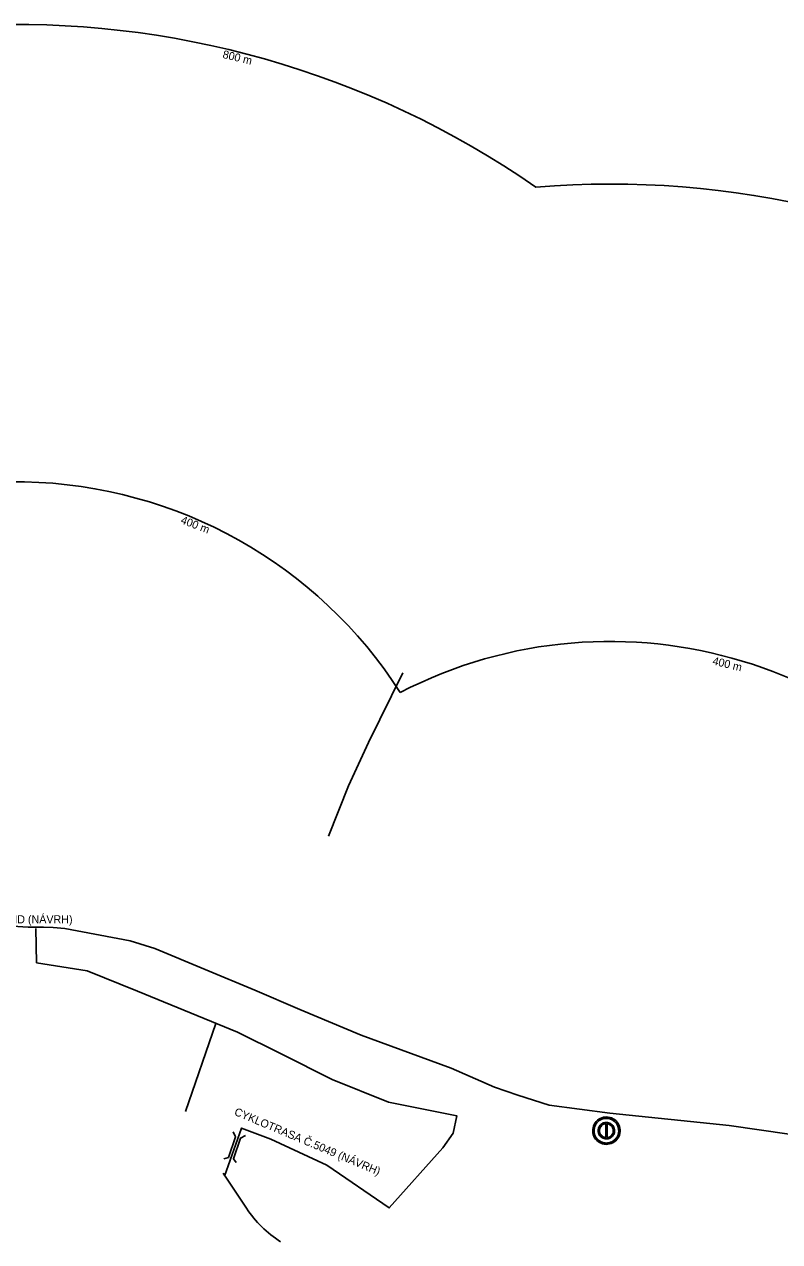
# Model space of a CAD drawing. Extents: x -520790 to -517278, y -1190021 to -1185077.
# Drawn here: x -518762 to -518101, y -1187441 to -1186376 of the extents above; entities that cross this region are included whole.
import ezdxf

# ---------------------------------------------------------------- set-up
doc = ezdxf.new("R2010")
doc.units = 0
for name, color, linetype in [('cyklostezka_n', 7, 'Continuous'), ('cyklostezka_s', 7, 'Continuous'), ('dostupnost_s', 7, 'Continuous'), ('most_s', 7, 'Continuous'), ('stezka_s', 7, 'Continuous'), ('zast_HD_n', 7, 'Continuous'), ('zast_HD_s', 7, 'Continuous')]:
    doc.layers.add(name, color=color, linetype=linetype)

msp = doc.modelspace()

# ---------------------------------------------------------------- linework, layer by layer
at = {"layer": 'cyklostezka_n'}
msp.add_lwpolyline([(-518752, -1187166.7), (-518751.3, -1187196.7), (-518706.9, -1187203.8), (-518663, -1187221.6), (-518575.5, -1187257.3), (-518537.2, -1187276.5), (-518492.8, -1187298.7), (-518443.4, -1187318.5), (-518383.7, -1187330.7), (-518386.8, -1187345.7), (-518395.9, -1187358.7), (-518442.8, -1187411.1), (-518497.5, -1187373.7), (-518546.3, -1187351.1), (-518572.1, -1187341.3), (-518587, -1187383.2)], dxfattribs=at)
at = {"layer": 'cyklostezka_s'}
msp.add_line((-518588.2, -1187380.6), (-518567.7, -1187411.4), dxfattribs=at)
msp.add_lwpolyline([(-518772.3, -1187164.7), (-518758.6, -1187165.5), (-518745.3, -1187165.7), (-518736.7, -1187165.9), (-518726.5, -1187166.8), (-518669.5, -1187177.6), (-518647.9, -1187184.2), (-518603.7, -1187202.5), (-518560.3, -1187220.6), (-518521, -1187237.6), (-518467.4, -1187259.9), (-518388.7, -1187289), (-518350.8, -1187305.5), (-518330.4, -1187312.4), (-518303.1, -1187321.2), (-518249.9, -1187328.2), (-518145.5, -1187338.9), (-518093, -1187346.5)], dxfattribs=at)
msp.add_arc((-518484.4, -1187356.1), 100, 213.5928, 237.6953, dxfattribs=at)
at = {"layer": 'dostupnost_s'}
for centre, radius, start, end in [((-518770, -1187176.1), 800, 55.3007, 129.8841), ((-518249.8, -1187315.8), 800, 238.9173, 94.6412), ((-518770, -1187176.1), 400, 32.6563, 144.9976), ((-518249.8, -1187315.8), 400, 212.6563, 117.2847)]:
    msp.add_arc(centre, radius, start, end, dxfattribs=at)
at = {"layer": 'most_s'}
for points in [[(-518579.4, -1187344.6), (-518577.3, -1187349), (-518583.5, -1187367), (-518587.4, -1187368.2)], [(-518568.4, -1187347.9), (-518572.8, -1187350), (-518579.1, -1187368.1), (-518576.8, -1187371.4)]]:
    msp.add_lwpolyline(points, dxfattribs=at)
at = {"layer": 'stezka_s'}
for points in [[(-518496, -1187085.9), (-518478.5, -1187041.9), (-518461, -1187004.2), (-518431, -1186943.2)], [(-518594.6, -1187249.8), (-518621.1, -1187326.8)]]:
    msp.add_lwpolyline(points, dxfattribs=at)
at = {"layer": 'zast_HD_s'}
msp.add_line((-518252.3, -1187350.7), (-518252.3, -1187350.7), dxfattribs=at)
for points in [[(-518252.9, -1187331.5), (-518253.9, -1187331.6), (-518255.4, -1187331.8), (-518256.9, -1187332.2), (-518258.3, -1187332.8), (-518259.6, -1187333.6), (-518260.8, -1187334.5), (-518261.9, -1187335.6), (-518262.8, -1187336.8), (-518263.6, -1187338.1), (-518264.2, -1187339.5), (-518264.6, -1187340.9), (-518264.9, -1187342.4), (-518264.9, -1187343.9), (-518264.8, -1187345.4), (-518264.4, -1187346.9), (-518263.9, -1187348.4), (-518263.2, -1187349.7), (-518262.4, -1187351), (-518261.4, -1187352.1), (-518260.2, -1187353.1), (-518259, -1187353.9), (-518257.6, -1187354.6), (-518256.2, -1187355.1), (-518254.7, -1187355.4), (-518253.2, -1187355.6), (-518251.7, -1187355.5), (-518250.2, -1187355.2), (-518248.7, -1187354.8), (-518247.3, -1187354.2), (-518246, -1187353.4), (-518244.8, -1187352.4), (-518243.8, -1187351.4), (-518242.9, -1187350.1), (-518242.1, -1187348.8), (-518241.5, -1187347.4), (-518241.2, -1187346), (-518240.9, -1187344.4), (-518240.9, -1187342.9), (-518241.1, -1187341.4), (-518241.5, -1187339.9), (-518242, -1187338.5), (-518242.7, -1187337.2), (-518243.6, -1187336), (-518244.7, -1187334.8), (-518245.8, -1187333.9), (-518247.1, -1187333.1), (-518248.5, -1187332.4), (-518249.9, -1187331.9), (-518251.4, -1187331.6), (-518252.9, -1187331.5)], [(-518252.9, -1187332.7), (-518252, -1187332.8), (-518250.7, -1187333), (-518249.3, -1187333.4), (-518248.1, -1187333.9), (-518246.9, -1187334.6), (-518245.8, -1187335.4), (-518244.9, -1187336.4), (-518244, -1187337.4), (-518243.3, -1187338.6), (-518242.8, -1187339.9), (-518242.4, -1187341.2), (-518242.2, -1187342.5), (-518242.1, -1187343.9), (-518242.2, -1187345.3), (-518242.5, -1187346.6), (-518243, -1187347.9), (-518243.6, -1187349.1), (-518244.4, -1187350.2), (-518245.3, -1187351.2), (-518246.3, -1187352.1), (-518247.5, -1187352.9), (-518248.7, -1187353.5), (-518250, -1187354), (-518251.3, -1187354.2), (-518252.7, -1187354.4), (-518254, -1187354.3), (-518255.4, -1187354.1), (-518256.7, -1187353.7), (-518258, -1187353.1), (-518259.1, -1187352.4), (-518260.2, -1187351.6), (-518261.1, -1187350.6), (-518262, -1187349.5), (-518262.6, -1187348.3), (-518263.2, -1187347), (-518263.5, -1187345.7), (-518263.7, -1187344.4), (-518263.7, -1187343), (-518263.6, -1187341.6), (-518263.2, -1187340.3), (-518262.7, -1187339), (-518262.1, -1187337.8), (-518261.3, -1187336.7), (-518260.4, -1187335.7), (-518259.3, -1187334.8), (-518258.2, -1187334.1), (-518256.9, -1187333.5), (-518255.6, -1187333.1), (-518254.3, -1187332.8), (-518252.9, -1187332.7)], [(-518242.1, -1187343.6), (-518242.2, -1187342.2), (-518242.5, -1187340.9), (-518242.9, -1187339.6), (-518243.5, -1187338.3), (-518244.2, -1187337.2), (-518245.1, -1187336.1), (-518246.1, -1187335.2), (-518247.2, -1187334.4), (-518248.4, -1187333.7), (-518249.7, -1187333.3), (-518251, -1187332.9), (-518252.3, -1187332.8), (-518253.7, -1187332.8), (-518255.1, -1187333), (-518256.4, -1187333.3), (-518257.7, -1187333.8), (-518258.8, -1187334.5), (-518259.9, -1187335.3), (-518260.9, -1187336.3), (-518261.8, -1187337.4), (-518262.5, -1187338.5), (-518263, -1187339.8), (-518263.4, -1187341.1), (-518263.7, -1187342.4), (-518263.7, -1187343.8), (-518263.6, -1187345.1), (-518263.3, -1187346.5), (-518262.9, -1187347.8), (-518262.3, -1187349), (-518261.5, -1187350.1), (-518260.6, -1187351.2), (-518259.6, -1187352.1), (-518258.5, -1187352.8), (-518257.2, -1187353.5), (-518256, -1187353.9), (-518254.6, -1187354.2), (-518253.3, -1187354.4), (-518251.9, -1187354.3), (-518250.5, -1187354.1), (-518249.2, -1187353.7), (-518248, -1187353.2), (-518246.8, -1187352.5), (-518245.7, -1187351.6), (-518244.8, -1187350.7), (-518243.9, -1187349.6), (-518243.3, -1187348.4), (-518242.7, -1187347.1), (-518242.3, -1187345.8), (-518242.1, -1187344.5), (-518242.1, -1187343.6)], [(-518253.5, -1187336.4), (-518254.4, -1187336.5), (-518255.3, -1187336.8), (-518256.2, -1187337.1), (-518256.9, -1187337.6), (-518257.7, -1187338.2), (-518258.3, -1187338.8), (-518258.9, -1187339.5), (-518259.3, -1187340.3), (-518259.7, -1187341.1), (-518259.9, -1187342), (-518260.1, -1187342.9), (-518260.1, -1187343.8), (-518260, -1187344.7), (-518259.8, -1187345.6), (-518259.5, -1187346.4), (-518259.1, -1187347.3), (-518258.6, -1187348), (-518258, -1187348.7), (-518257.3, -1187349.3), (-518256.5, -1187349.8), (-518255.7, -1187350.2), (-518254.8, -1187350.5), (-518254, -1187350.7), (-518253.1, -1187350.7), (-518252.3, -1187350.7)], [(-518253.5, -1187349.6), (-518254.2, -1187349.4), (-518255, -1187349.2), (-518255.7, -1187348.9), (-518256.3, -1187348.5), (-518256.9, -1187348.1), (-518257.5, -1187347.5), (-518257.9, -1187346.9), (-518258.3, -1187346.3), (-518258.6, -1187345.6), (-518258.8, -1187344.8), (-518258.9, -1187344.1), (-518259, -1187343.3), (-518258.9, -1187342.5), (-518258.7, -1187341.8), (-518258.4, -1187341.1), (-518258.1, -1187340.4), (-518257.6, -1187339.8), (-518257.1, -1187339.2), (-518256.5, -1187338.7), (-518255.9, -1187338.3), (-518255.2, -1187338), (-518254.5, -1187337.7), (-518253.7, -1187337.6), (-518253.5, -1187337.6)], [(-518252.3, -1187350.7), (-518251.4, -1187350.6), (-518250.5, -1187350.3), (-518249.7, -1187350), (-518248.9, -1187349.5), (-518248.2, -1187349), (-518247.5, -1187348.3), (-518247, -1187347.6), (-518246.5, -1187346.8), (-518246.2, -1187346), (-518245.9, -1187345.1), (-518245.8, -1187344.2), (-518245.7, -1187343.3), (-518245.8, -1187342.4), (-518246, -1187341.5), (-518246.3, -1187340.7), (-518246.8, -1187339.9), (-518247.3, -1187339.1), (-518247.9, -1187338.4), (-518248.6, -1187337.8), (-518249.3, -1187337.3), (-518250.1, -1187336.9), (-518251, -1187336.6), (-518251.9, -1187336.4), (-518252.8, -1187336.4), (-518253.5, -1187336.4)], [(-518253.5, -1187336.4), (-518253.5, -1187349.6)], [(-518253.5, -1187337.6), (-518253.5, -1187336.4)], [(-518252.9, -1187331.5), (-518252.9, -1187332.7)], [(-518252.9, -1187332.7), (-518252.9, -1187331.5)], [(-518252.3, -1187350.7), (-518252.3, -1187337.5)], [(-518252.3, -1187337.5), (-518251.6, -1187337.7), (-518250.9, -1187337.9), (-518250.2, -1187338.2), (-518249.5, -1187338.6), (-518248.9, -1187339.1), (-518248.4, -1187339.6), (-518247.9, -1187340.2), (-518247.5, -1187340.9), (-518247.2, -1187341.6), (-518247, -1187342.3), (-518246.9, -1187343.1), (-518246.9, -1187343.8), (-518247, -1187344.6), (-518247.1, -1187345.3), (-518247.4, -1187346), (-518247.8, -1187346.7), (-518248.2, -1187347.3), (-518248.7, -1187347.9), (-518249.3, -1187348.4), (-518249.9, -1187348.8), (-518250.6, -1187349.1), (-518251.3, -1187349.4), (-518252.1, -1187349.5), (-518252.3, -1187349.6)], [(-518252.3, -1187349.6), (-518252.3, -1187350.7)]]:
    msp.add_lwpolyline(points, dxfattribs=at)

# ---------------------------------------------------------------- texts
at = {"layer": 'cyklostezka_n'}
msp.add_text('CYKLOTRASA Č.5049 (NÁVRH)', height=7, rotation=337.2199, dxfattribs=at).set_placement((-518579, -1187329.6))
at = {"layer": 'dostupnost_s'}
for s, rotation, p in [('800 m', 346.4234, (-518589, -1186405.4)), ('400 m', 338.7751, (-518625.8, -1186812.2)), ('400 m', 346.4234, (-518160.6, -1186935.8))]:
    msp.add_text(s, height=7, rotation=rotation, dxfattribs=at).set_placement(p)
at = {"layer": 'zast_HD_n'}
msp.add_text('ZASTÁVKA HD (NÁVRH)', height=7, dxfattribs=at).set_placement((-518826.4, -1187162.2))

doc.saveas('drawing.dxf')
